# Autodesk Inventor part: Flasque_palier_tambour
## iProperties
Shininess: 64.0
Length Units: 11269
Angle Units: 11279
Time Units: 11290
Mass Units: 11283
Length Display Precision: 3
Angle Display Precision: 2
Compacted: True
Part Number: Flasque_palier_tambour
Document SubType Name: Modeling
Created: 2008-02
Material: Acier inoxydable, austénitique
Designer: Pascal
Density: 0.0
Volumn: 0.0
Area: 0.0
PropertySet Name: Model Information
Control State: 0
Master: False
Checked Out: False
DESIGNATION: pièce
Author: Pascal
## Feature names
1. Extrusion1
2. Extrusion2
3. Chanfrein1 [Chamfer]
4. Extrusion3
